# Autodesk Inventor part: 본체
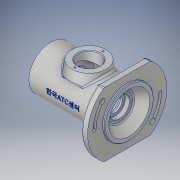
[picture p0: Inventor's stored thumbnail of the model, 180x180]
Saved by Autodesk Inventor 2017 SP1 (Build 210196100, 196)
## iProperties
Part Number: 본체
Material: 알루미늄 6061
Document SubType Name: Modeling
Designer: MRC
Density: 2.7 g/cm^3
Appearance: 알루미늄 - 평지
Author: MRC
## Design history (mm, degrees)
sketch "스케치1"
  geometry: C1 r 58 at (0, 0); 1 further point
  constraints: 1 centre point, 1 coincident
  dimensions: "d0" = 116 diameter of C1
extrude "돌출1" new body sketch "스케치1" distance "d1" = 10; taper "d2" = 0 deg
sketch "스케치2"
  geometry: L1 (-33.985, 47)-(33.985, 47); L2 (-33.985, -47)-(33.985, -47); L3 (-58, 0)-(0, 0); A1 r 58 centre (0, 0) between (33.985, 47) and (-33.985, -47) reference; A2 r 58 centre (0, 0) between (33.985, 47) and (-33.985, 47); A3 r 58 centre (0, 0) between (-33.985, -47) and (33.985, -47); 3 further points
  constraints: 8 point on circle, 6 end point, 3 coincident, 2 centre point, 2 horizontal, 2 midpoint, 2 vertical alignment, 1 parallel, 1 other
  dimensions: "d3" = 94 distance between parallel lines of L2 L1
extrude "돌출2" cut sketch "스케치2" distance "d4" = 10; taper "d5" = 0 deg
sketch "스케치3"
  geometry: C1 r 32 at (0, 0); 1 further point
  constraints: 1 centre point, 1 coincident
  dimensions: "d6" = 64 diameter of C1
extrude "돌출3" join sketch "스케치3" distance "d7" = 102; taper "d8" = 0 deg
sketch "스케치6"
  geometry: L1 (-46, 38)-(-46, 20.549); L2 (-46, 20.549)-(-17.923, 20.549); L3 (-17.923, 20.549)-(-21, 38); L4 (-21, 38)-(-46, 38); L5 (0, 32)-(-102, 32) reference; L6 (-17.923, 20.549)-(-17.923, 32); L7 (-102, 32)-(-102, -32) reference; 1 further point
  constraints: 10 end point, 2 vertical, 1 parallel, 1 perpendicular, 1 point on line
  dimensions: "d18" = 38 distance from line of point (0, 0) L4; "d20" = 10 deg angle of L6 L3; "d22" = 56 distance from line of L1.end L7; "d23" = 17.45084 vertical distance of L2.end L3.end; "d123" = 50 diameter of L3.end L1
revolve "회전1" sketch "스케치6" stored, may be unused: angle "d24" = 90 deg
sketch "스케치7"
  geometry: 2 further points
  constraints: 1 coincident
hole "구멍1" sketch "스케치7" at (0, 0) diameter "d25" = 43.376; stored, may be unused: countersink angle "d29" = 90 deg, drill point angle "d31" = 118 deg; dims "d26" = 7, "d27" = 4, "d28" = 2, "d30" = 8
sketch "스케치9"
  geometry: C1 r 36 at (0, 0); 1 further point
  constraints: 1 centre point, 1 coincident
  dimensions: "d32" = 72 diameter of C1
extrude "돌출5" join sketch "스케치9" distance "d33" = 3; taper "d34" = 0 deg
sketch "스케치8"
  geometry: L1 (-102, 0)-(13, 0); L2 (-94, 0)-(-94, 24); L3 (-94, 24)-(-91, 24); L4 (-91, 24)-(-91, 22.5); L5 (-91, 22.5)-(-83, 22.5); L6 (-80, 19.5)-(-80, 18.5); L7 (-79, 17.5)-(-77.75, 17.5); L8 (-77.75, 17.5)-(-77.75, 18.5); L9 (-77.75, 18.5)-(-76, 18.5); L10 (-76, 18.5)-(-76, 17.5); L11 (-76, 17.5)-(-66, 17.5); L12 (-65, 18.5)-(-65, 27); L13 (-65, 27)-(-27, 27); L14 (-27, 27)-(-27, 18.5); L15 (13, -36)-(13, 36) reference; L16 (13, 30)-(13, 0); L17 (-102, -21.688)-(-102, 21.688) reference; L18 (-26, 17.5)-(-16.6, 17.5); L19 (-16, 16.9)-(-16, 15); L20 (-16, 15)-(-14, 15); L21 (-11, 12)-(-11, 11); L22 (-11, 11)-(-8.3, 11); L23 (-8.3, 11)-(-8.3, 14.5); L24 (-7.8, 15)-(-1.7, 15); L25 (-1, 15.404)-(-1, 20); L26 (-1, 20)-(13, 30); L27 (-80, 18.5)-(-79, 17.5); L28 (-65, 18.5)-(-66, 17.5); L29 (-27, 18.5)-(-26, 17.5); L30 (-1.7, 15)-(-1, 15.404); A1 r 3 centre (-83, 19.5) between (-80, 19.5) and (-83, 22.5); A2 r 0.6 centre (-16.6, 16.9) between (-16, 16.9) and (-16.6, 17.5); A3 r 3 centre (-14, 12) between (-11, 12) and (-14, 15); A4 r 0.5 centre (-7.8, 14.5) between (-7.8, 15) and (-8.3, 14.5); 9 further points
  constraints: 56 end point, 18 point on line, 17 perpendicular, 8 point on circle, 8 tangent, 4 centre point, 2 horizontal, 2 midpoint, 1 collinear, 1 horizontal alignment, 1 vertical
  dimensions: "d35" = 3 distance of L2.end L3.end; "d36" = 48 diameter of L3 L1; "d37" = 45 diameter of L5 L1; "d38" = 22 distance between parallel lines of L6 L17; "d39" = 1.75 distance of L8.end L9.end; "d40" = 4 distance between parallel lines of L10 L6; "d41" = 11 distance between parallel lines of L12 L10; "d42" = 37 diameter of L9 L1; "d43" = 35 diameter of L7 L1; "d44" = 54 diameter of L13 L1; "d45" = 38 distance of L12.end L13.end; "d46" = 11 distance of point (-27, 17.5) point (-16, 17.5); "d47" = 14 horizontal distance of L16.start L25.end; "d48" = 5 distance of L19.end point (-11, 15); "d49" = 29 distance between parallel lines of L15 L19 (derived); "d50" = 22 diameter of L22 L1; "d51" = 30 diameter of L20 L1; "d52" = 35 diameter of L18 L1; "d53" = 30 diameter of L24 L1; "d54" = 40 diameter of L25.end L1; "d55" = 60 diameter of L16.start L1; "d56" = 107 distance between parallel lines of L15 L2; "d65" = 3 radius of A1; "d66" = 1 distance of L6.end point (-80, 17.5); "d67" = 1 distance of L7.start point (-80, 17.5) (= d66); "d68" = 1 distance of L12.start point (-65, 17.5); "d69" = 1 distance of L11.end point (-65, 17.5) (= d68); "d70" = 1 distance of L14.end point (-27, 17.5); "d71" = 1 distance of L18.start point (-27, 17.5) (= d70); "d72" = 0.6 radius of A2; "d73" = 3 radius of A3; "d74" = 0.5 radius of A4; "d75" = 7.3 distance between parallel lines of L25 L23; "d76" = 0.7 horizontal distance of L25.start L24.end; "d77" = 30 deg angle of L24 L30
revolve "회전2" sketch "스케치8" stored, may be unused: angle "d58" = 90 deg
sketch "스케치10"
  geometry: C1 r 25 at (0, 0) reference; C2 r 16 at (0, 0); 1 further point
  constraints: 1 centre point, 1 coincident
  dimensions: "d59" = 32 diameter of C2
extrude "돌출6" cut sketch "스케치10" distance "d60" = 30; taper "d61" = 0 deg
chamfer "모따기1" distance "d62" = 1; stored, may be unused: second distance "d63" = 2, angle "d64" = 45 deg
fillet "모깎기1" dims "d78" = 3
sketch "스케치11"
  geometry: L1 (-36.77, -30.854)-(36.77, 30.854); L2 (0, 0)-(0, 48); L3 (-33.985, 47)-(33.985, 47) reference; L4 (0, 0)-(48, 0); A1 r 48 centre (0, 0) between (36.77, 30.854) and (0, 48); 3 further points
  constraints: 6 end point, 4 point on circle, 3 coincident, 1 centre point, 1 horizontal, 1 midpoint, 1 perpendicular
  dimensions: "d80" = 96 diameter of A1; "d81" = 40 deg angle of L4 L1
hole "구멍2" sketch "스케치11" at (36.77, 30.854), (-36.77, -30.854) diameter "d82" = 4.5; stored, may be unused: countersink angle "d86" = 90 deg, drill point angle "d88" = 118 deg; dims "d83" = 7, "d84" = 8, "d85" = 4.4, "d87" = 10
sketch "스케치12"
  geometry: L1 (-48, 0)-(48, 0); L2 (-36.77, -30.854)-(36.77, 30.854); A1 r 48 centre (0, 0) between (48, 0) and (36.77, 30.854); A2 r 48 centre (0, 0) between (48, 0) and (36.77, 30.854); A3 r 52 centre (0, 0) between (52, 0) and (39.834, 33.425); A4 r 44 centre (0, 0) between (44, 0) and (33.706, 28.283); A5 r 4 centre (48, 0) between (44, 0) and (52, 0); A6 r 4 centre (36.77, 30.854) between (39.834, 33.425) and (33.706, 28.283); A7 r 48 centre (0, 0) between (-48, 0) and (-36.77, -30.854); A8 r 52 centre (0, 0) between (-52, 0) and (-39.834, -33.425); A9 r 44 centre (0, 0) between (-44, 0) and (-33.706, -28.283); A10 r 4 centre (-48, 0) between (-44, 0) and (-52, 0); A11 r 4 centre (-36.77, -30.854) between (-39.834, -33.425) and (-33.706, -28.283); 1 further point
  constraints: 24 point on circle, 11 centre point, 8 tangent, 4 end point, 3 concentric, 2 midpoint, 1 coincident, 1 horizontal
  dimensions: "d89" = 96 diameter of A1; "d90" = 40 deg angle of L1 L2; "d91" = 4 radius of A6; "d92" = 4 radius of A11
extrude "돌출7" cut sketch "스케치12" distance "d93" = 4.4; taper "d94" = 0 deg
sketch "스케치13"
  geometry: L1 (-33.985, 47)-(33.985, 47) reference; L2 (48, 0)-(-48, 0); L3 (36.77, -30.854)-(-36.77, 30.854); C1 r 2.25 at (-36.77, 30.854) reference; A1 r 48 centre (0, 0) between (48, 0) and (36.77, -30.854); A2 r 4 centre (-48, 0) between (-52, 0) and (-44, 0) reference; A3 r 48 centre (0, 0) between (-36.77, 30.854) and (-48, 0); A4 r 50.25 centre (0, 0) between (-38.494, 32.3) and (-50.25, 0); A5 r 45.75 centre (0, 0) between (-35.047, 29.408) and (-45.75, 0); A6 r 2.25 centre (-36.77, 30.854) between (-35.047, 29.408) and (-38.494, 32.3); A7 r 2.25 centre (-48, 0) between (-50.25, 0) and (-45.75, 0); A8 r 48 centre (0, 0) between (36.77, -30.854) and (48, 0); A9 r 50.25 centre (0, 0) between (38.494, -32.3) and (50.25, 0); A10 r 45.75 centre (0, 0) between (35.047, -29.408) and (45.75, 0); A11 r 2.25 centre (36.77, -30.854) between (35.047, -29.408) and (38.494, -32.3); A12 r 2.25 centre (48, 0) between (50.25, 0) and (45.75, 0); 1 further point
  constraints: 22 point on circle, 11 centre point, 8 tangent, 4 end point, 2 concentric, 2 midpoint, 1 coincident, 1 horizontal
  dimensions: "d95" = 96 diameter of A1; "d96" = 2.25 radius of A6; "d97" = 2.25 radius of A11
extrude "돌출8" cut sketch "스케치13" distance "d98" = 5.6; taper "d99" = 0 deg
sketch "스케치14"
  geometry: L1 (-48, 0)-(48, 0); L2 (-36.77, -30.854)-(36.77, 30.854); C1 r 4 at (36.77, 30.854); C2 r 4 at (-36.77, -30.854); A1 r 48 centre (0, 0) between (-48, 0) and (-36.77, -30.854); A2 r 2.25 centre (48, 0) between (45.75, 0) and (50.25, 0) reference; A3 r 2.25 centre (36.77, 30.854) between (38.494, 32.3) and (35.047, 29.408) reference; 1 further point
  constraints: 4 end point, 3 centre point, 3 coincident, 2 midpoint, 2 point on circle, 1 horizontal
  dimensions: "d100" = 96 diameter of A1; "d101" = 8 diameter of C1; "d102" = 8 diameter of C2
extrude "돌출9" cut sketch "스케치14" distance "d103" = 10; taper "d104" = 0 deg
fillet "모깎기3" dims "d105" = 3
fillet "모깎기4" dims "d106" = 3
fillet "모깎기5" dims "d107" = 3
chamfer "모따기2" distance "d108" = 1; stored, may be unused: second distance "d109" = 2, angle "d110" = 45 deg
sketch "스케치15"
  geometry: C1 r 25 at (0, 0) reference; A1 r 20.5 centre (0, 0) between (0, 20.5) and (0, -20.5); 1 further point
  constraints: 2 point on circle, 2 vertical alignment, 1 centre point, 1 coincident
  dimensions: "d111" = 41 diameter of A1
hole "구멍3" sketch "스케치15" at (0, 20.5), (0, -20.5) diameter "d112" = 2.459; stored, may be unused: countersink angle "d116" = 90 deg, drill point angle "d118" = 118 deg; dims "d113" = 6, "d114" = 4, "d115" = 2, "d117" = 8
node "작업 평면3"
sketch "스케치16"
  geometry: L1 (10, -46.4)-(10, 46.4) reference; 2 further points
  constraints: 1 horizontal alignment, 1 other
  dimensions: "d120" = 62 distance from line of L1 point (-52, 0)
feature "엠보싱1" sketch "스케치16" dims "d121" = 0.5, "d122" = 0
fillet "모깎기6" dims "d124" = 3
fillet "모깎기7" dims "d125" = 3
node "솔리드1"
other parameters: "d119" = 32
